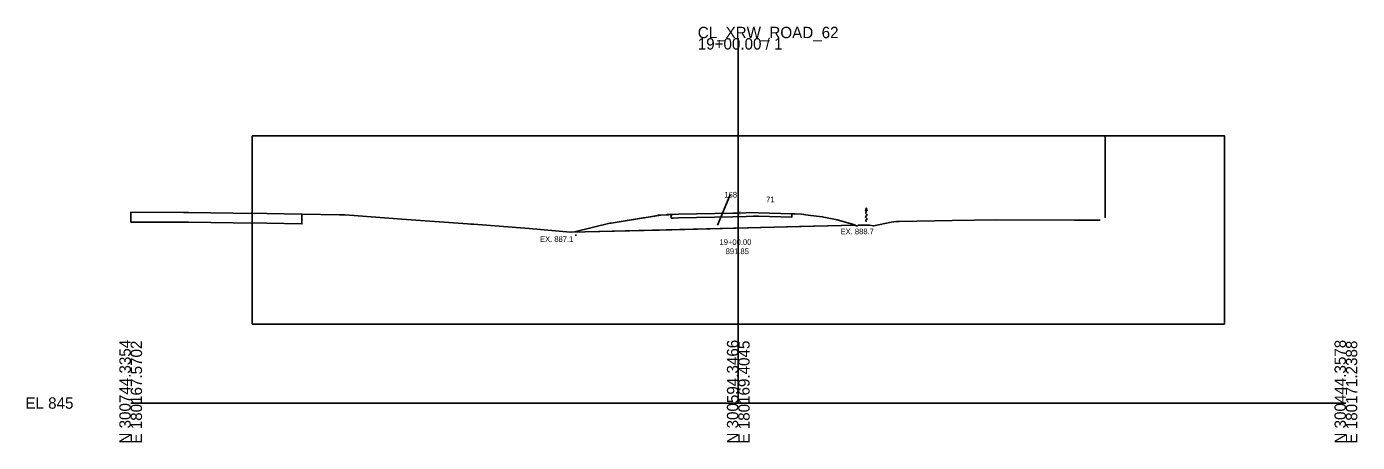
# Model space of a CAD drawing. Extents: x -26 to 180171, y 490 to 300744.
# Drawn here: x -25.7 to 302.8, y 3990.3 to 4092.8 of the extents above; entities that cross this region are included whole.
import ezdxf

# ---------------------------------------------------------------- set-up
doc = ezdxf.new("R2010")
doc.units = 0
for name, color, linetype in [('Default', 7, 'Continuous'), ('DT_P_Break_Line', 7, 'Continuous'), ('DT_P_TIN_Hull', 7, 'Continuous'), ('DT_P_Void', 7, 'Continuous'), ('DT_X_Void', 7, 'Continuous'), ('GK_Patterns', 7, 'Continuous'), ('MD_P_Subgrade', 7, 'Continuous'), ('MD_P_Surface_Aggregate_Base', 7, 'Continuous'), ('MD_P_Surface_Asphalt_Concrete_Base', 7, 'Continuous'), ('PM_P_Edge_Line', 7, 'Continuous'), ('PV_X_Saw_Cut_Line', 7, 'Continuous'), ('RD_P_Fence', 7, 'Continuous'), ('RW_P_Esmt_LA', 7, 'Continuous'), ('RW_X_CL_50', 7, 'Continuous'), ('SC_Scratch1', 7, 'Continuous'), ('SV_X_Control_Cells_Found', 7, 'Continuous'), ('SV_X_Text_Name', 7, 'Continuous'), ('TX_P_1', 7, 'Continuous')]:
    doc.layers.add(name, color=color, linetype=linetype)

msp = doc.modelspace()

# ---------------------------------------------------------------- linework, layer by layer
at = {"layer": 'DT_P_Break_Line'}
msp.add_lwpolyline([(51.95, 4046.39), (51.65, 4046.39)], dxfattribs=at)
at = {"layer": 'DT_P_Void'}
msp.add_lwpolyline([(30, 4065.91), (270, 4065.91), (270, 4019.48), (30, 4019.48)], close=True, dxfattribs=at)
at = {"layer": 'DT_X_Void'}
for p, q in [((150, 4000), (150, 4090)), ((0, 4000), (150, 4000)), ((150, 4000), (300, 4000))]:
    msp.add_line(p, q, dxfattribs=at)
at = {"layer": 'GK_Patterns'}
msp.add_line((108.8, 4042.14), (178.86, 4043.85), dxfattribs=at)
at = {"layer": 'MD_P_Subgrade'}
for p, q in [((181.59, 4048.17), (181.37, 4047.37)), ((181.8, 4047.37), (181.59, 4048.17))]:
    msp.add_line(p, q, dxfattribs=at)
msp.add_spline([(181.59, 4048.17), (181.59, 4047.34), (181.51, 4047.01), (181.44, 4046.8), (181.81, 4046.37), (181.39, 4045.89), (181.81, 4045.33), (181.58, 4045.22), (181.59, 4044.67)], degree=3, dxfattribs=at)
at = {"layer": 'MD_P_Surface_Asphalt_Concrete_Base'}
msp.add_lwpolyline([(151.95, 4046.9), (148.68, 4046.82), (135.28, 4046.55), (133.89, 4046.49), (133.45, 4046.49), (133.45, 4045.64), (133.89, 4045.64), (135.28, 4045.69), (148.68, 4045.96), (151.95, 4046.05), (153.79, 4046.11), (154.99, 4046.07), (163.21, 4045.81), (163.21, 4046.66), (154.99, 4046.92), (153.79, 4046.96), (151.95, 4046.9)], dxfattribs=at)
at = {"layer": 'PV_X_Saw_Cut_Line'}
for points in [[(126.84, 4045.7), (126.54, 4045.7)], [(110.06, 4041.41), (109.76, 4041.41)]]:
    msp.add_lwpolyline(points, dxfattribs=at)
at = {"layer": 'RD_P_Fence'}
for points in [[(0, 4044.65), (0, 4047.06), (0, 4047.06), (13.02, 4047.02), (13.02, 4047.02), (13.65, 4047.02), (13.65, 4047.02), (14.25, 4047.02), (14.25, 4047.02), (25.33, 4046.85), (25.33, 4046.85), (33.62, 4046.75), (33.62, 4046.75), (42.28, 4046.6), (42.28, 4046.6), (42.28, 4044.18), (42.28, 4044.18), (33.62, 4044.33), (33.62, 4044.33), (25.33, 4044.43), (25.33, 4044.43), (14.25, 4044.6), (14.25, 4044.6), (13.65, 4044.6), (13.65, 4044.6), (13.02, 4044.6), (13.02, 4044.6), (0, 4044.65)], [(153.79, 4046.96), (154.99, 4046.92), (163.21, 4046.66), (163.21, 4045.81), (154.99, 4046.07), (153.79, 4046.11), (151.95, 4046.05), (148.68, 4045.96), (135.28, 4045.69), (133.89, 4045.64), (133.45, 4045.64), (133.45, 4046.49), (133.89, 4046.49), (135.28, 4046.55), (148.68, 4046.82), (151.95, 4046.9), (153.79, 4046.96)]]:
    msp.add_lwpolyline(points, dxfattribs=at)
at = {"layer": 'RW_P_Esmt_LA'}
for points in [[(0, 4047.06), (13.02, 4047.02), (13.65, 4047.02), (14.25, 4047.02), (25.33, 4046.85), (33.62, 4046.75), (42.28, 4046.6)], [(133.45, 4046.49), (133.89, 4046.49), (135.28, 4046.55), (148.68, 4046.82), (151.95, 4046.9), (153.79, 4046.96), (154.99, 4046.92), (163.21, 4046.66)]]:
    msp.add_lwpolyline(points, dxfattribs=at)
at = {"layer": 'RW_X_CL_50'}
for points in [[(130.46, 4046.38), (130.16, 4046.38)], [(132.76, 4046.51), (132.46, 4046.51)]]:
    msp.add_lwpolyline(points, dxfattribs=at)
at = {"layer": 'SC_Scratch1'}
msp.add_lwpolyline([(0, 4047.06), (13.02, 4047.02), (13.65, 4047.02), (14.25, 4047.02), (25.33, 4046.85), (33.62, 4046.75), (42.28, 4046.6), (51.57, 4046.42), (52.08, 4046.41), (52.92, 4046.39), (66.94, 4045.32), (83.19, 4044.17), (83.95, 4044.12), (84.66, 4044.09), (98.37, 4043.08), (108.55, 4042.12), (109.6, 4042.21), (118.29, 4044.33), (118.64, 4044.37), (121.09, 4044.76), (130.88, 4046.37), (133.45, 4046.49), (133.89, 4046.49), (135.28, 4046.55), (148.68, 4046.82), (150, 4046.85), (151.95, 4046.9), (153.79, 4046.96), (154.99, 4046.92), (163.21, 4046.66), (164.01, 4046.67), (165.62, 4046.61), (167.27, 4046.35), (170.72, 4045.96), (174.38, 4045.16), (178.19, 4044.12), (179.33, 4043.67), (179.56, 4043.86), (182.37, 4043.89), (183.46, 4043.7), (187.74, 4044.58), (189.08, 4044.82), (189.68, 4044.82), (202.82, 4045.03), (213.67, 4045.17), (232.97, 4045.1), (233.8, 4045.08), (235.25, 4045.1), (235.87, 4045.09), (236.6, 4045.11), (237.4, 4045.12), (239.33, 4045.15)], dxfattribs=at)
at = {"layer": 'SV_X_Control_Cells_Found'}
msp.add_line((240.59, 4065.72), (240.59, 4045.72), dxfattribs=at)
at = {"layer": 'SV_X_Text_Name'}
for p, q in [((144.84, 4043.87), (148.03, 4051.39)), ((126.84, 4045.7), (126.78, 4045.7)), ((108.55, 4042.12), (112.13, 4042.22)), ((112.13, 4042.22), (115.86, 4042.31)), ((115.86, 4042.31), (130.5, 4042.67)), ((130.5, 4042.67), (165.08, 4043.52)), ((165.08, 4043.52), (178.86, 4043.85)), ((178.86, 4043.85), (178.19, 4044.12))]:
    msp.add_line(p, q, dxfattribs=at)
for points in [[(126.78, 4045.7), (126.55, 4045.66), (121.09, 4044.76), (118.64, 4044.37), (118.29, 4044.33), (109.6, 4042.21), (108.55, 4042.12)], [(133.45, 4046.49), (133.06, 4046.47), (132.76, 4046.46), (132.46, 4046.45), (130.88, 4046.37), (130.77, 4046.35), (130.47, 4046.31), (126.84, 4045.71)], [(126.84, 4045.71), (126.84, 4045.7)], [(154.99, 4046.07), (153.79, 4046.11), (151.95, 4046.05), (148.68, 4045.96), (135.28, 4045.69), (133.89, 4045.64), (133.45, 4045.64), (133.45, 4046.49)], [(163.21, 4046.66), (163.21, 4045.81), (154.99, 4046.07)], [(178.19, 4044.12), (174.38, 4045.16), (170.72, 4045.96), (167.27, 4046.35), (165.62, 4046.61), (164.01, 4046.67), (163.21, 4046.66)]]:
    msp.add_lwpolyline(points, dxfattribs=at)
at = {"layer": 'TX_P_1'}
for points in [[(130.76, 4046.38), (130.46, 4046.38)], [(133.06, 4046.51), (132.76, 4046.51)]]:
    msp.add_lwpolyline(points, dxfattribs=at)

# ---------------------------------------------------------------- texts
at = {"layer": 'Default'}
msp.add_text('-', height=0.0001, dxfattribs=at).set_placement((0, 4000))
at = {"layer": 'DT_P_TIN_Hull'}
for s, p in [('19+00.00', (145.37, 4039)), ('891.85', (146.89, 4036.73))]:
    msp.add_text(s, height=1.4, dxfattribs=at).set_placement(p)
at = {"layer": 'DT_X_Void'}
for s, p in [('CL_XRW_ROAD_62', (140, 4090)), ('19+00.00 / 1', (140, 4087.2)), ('EL 845', (-26, 3998.6))]:
    msp.add_text(s, height=2.8, dxfattribs=at).set_placement(p)
for s, p in [('N 300744.3354', (0, 3990)), ('E 180167.5702', (2.8, 3990)), ('N 300594.3466', (150, 3990)), ('E 180169.4045', (152.8, 3990)), ('N 300444.3578', (300, 3990)), ('E 180171.2388', (302.8, 3990))]:
    msp.add_text(s, height=2.8, rotation=90, dxfattribs=at).set_placement(p)
at = {"layer": 'MD_P_Surface_Aggregate_Base'}
for s, p in [('EX. 887.1', (101.05, 4039.74)), ('EX. 888.7', (175.25, 4041.63))]:
    msp.add_text(s, height=1.4, dxfattribs=at).set_placement(p)
at = {"layer": 'PM_P_Edge_Line'}
msp.add_text('X', height=1, dxfattribs=at).set_placement((149.7, 4046.35))
at = {"layer": 'SV_X_Text_Name'}
for s, p in [('168', (146.57, 4050.69)), ('71', (156.87, 4049.53))]:
    msp.add_text(s, height=1.4, dxfattribs=at).set_placement(p)

doc.saveas('drawing.dxf')
